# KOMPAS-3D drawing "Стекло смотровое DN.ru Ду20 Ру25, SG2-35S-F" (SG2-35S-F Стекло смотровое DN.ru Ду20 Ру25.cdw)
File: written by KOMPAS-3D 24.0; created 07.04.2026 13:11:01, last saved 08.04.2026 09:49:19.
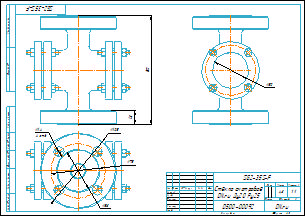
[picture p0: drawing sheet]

Document properties: Автор: Main; Форматы листов документа: A3; Полное имя файла: SG2-35S-F Стекло смотровое DN.ru Ду20 Ру25.m3d; Масса: 4.8; Наименование: Стекло смотровое DN.ru Ду20 Ру25; Количество листов документа: 1; Примечание: D500-00092

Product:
- Body: Тело 1  | qty 1
    Масса: 3.869459
- Part/product: Стекло смотровое DN.ru Ду20 Ру25  | designation SG2-35S-F
    Масса: 4.8
    Раздел спецификации: Прочие изделия
    Примечание: D500-00092

Views: Вид 1, Снизу, Проекционный вид 2
Referenced files in D:\DN.ru Аутсерс\Стекло смотровое DN.ru\Стекло смотровое DN.ru SG2-34G-F тип В ГОСТ 21836-2021 Ду100 Ру16, углеродистая сталь, фланцевое\: SG2-34G-F тип В Стекло смотровое DN.ru Ду100 Ру16.m3d, SG2-34G-F тип ВСтекло смотровое DN.ru Ду100 Ру16.cdw
Referenced files in D:\DN.ru Аутсерс\Стекло смотровое DN.ru\SG2-35S-F Стекло смотровое DN.ru Ду20 Ру25\: SG2-35S-F Стекло смотровое DN.ru Ду20 Ру25.m3d
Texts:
  SG2-35S-F
  Стекло смотровое
  DN.ru Ду20 Ру25
  Стекло смотровое DN.ru Ду20 Ру25
  SG2-35S-F Стекло смотровое DN.ru Ду20 Ру25
Dimensions and other numbers on the sheet: 0; 3; 2; 4; 150; 18; 14; 4 отв.; 105; 75; 58; 1:1; 1; 4,8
